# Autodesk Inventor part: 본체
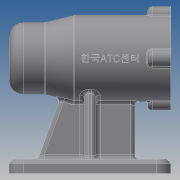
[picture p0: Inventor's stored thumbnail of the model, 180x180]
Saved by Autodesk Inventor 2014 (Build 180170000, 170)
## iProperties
Created: 2019-07
Part Number: 본체
Material: Generic
Document SubType Name: Modeling
Designer: kb541-07
Density: 1 g/cm^3
Appearance: Default
Author: kb541-07
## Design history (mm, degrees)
sketch "스케치1"
  geometry: L1 (-56, 0)-(56, 0); L2 (-56, 0)-(-56, 25); L3 (-56, 25)-(-31, 25); L4 (-31, 25)-(-11, 30); L5 (-11, 30)-(56, 30); L6 (56, 30)-(56, 0); 2 further points
  constraints: 12 end point, 2 perpendicular, 1 coincident, 1 horizontal, 1 midpoint, 1 parallel, 1 vertical
  dimensions: "d0" = 112 distance of L1.start L1.end; "d1" = 50 diameter of L3 L1; "d2" = 60 diameter of L5 L1; "d3" = 25 distance of L2.end L3.end; "d4" = 45 horizontal distance of L2.end L4.end
revolve "회전1" sketch "스케치1" stored, may be unused: angle "d5" = 90 deg
sketch "스케치2"
  geometry: C1 r 6 at (0, 30); C2 r 6 at (-30, 0); C3 r 6 at (0, -30); C4 r 6 at (30, 0); A1 r 30 centre (0, 0) between (0, 30) and (-30, 0) reference
  constraints: 4 centre point, 4 point on circle, 3 equal radius, 2 horizontal alignment, 2 vertical alignment
  dimensions: "d6" = 12 diameter of C1
extrude "돌출1" join sketch "스케치2" distance "d7" = 16; taper "d8" = 0 deg
sketch "스케치3"
  geometry: L1 (-56, -25)-(-56, 25) reference; L2 (-56, 25)-(-31, 25) reference; L3 (-31, 25)-(-11, 30) reference; L4 (-11, 30)-(40, 30) reference; L5 (40, 30)-(40, 36) reference; L6 (40, 36)-(56, 36) reference; L7 (56, 36)-(56, -36) reference; L8 (56, -36)-(40, -36) reference; L9 (40, -36)-(40, -30) reference; L10 (40, -30)-(-11, -30) reference; L11 (-11, -30)-(-31, -25) reference; L12 (-31, -25)-(-56, -25) reference; L13 (-56, 0)-(56, 0); L14 (-50, 0)-(-50, 10.5); L15 (-50, 10.5)-(-47, 10.5); L16 (-47, 10.5)-(-47, 16); L17 (-47, 16)-(-43, 16); L18 (-43, 16)-(-43, 17.5); L19 (-43, 17.5)-(-25, 17.5); L20 (-25, 17.5)-(-25, 21); L21 (-25, 21)-(-13, 21); L22 (-13, 21)-(-13, 24); L23 (-13, 24)-(41, 24); L24 (41, 24)-(41, 21); L25 (41, 21)-(56, 21); L26 (56, 21)-(56, 0); L27 (56, 5.97)-(56, 29.4) reference; 1 further point
  constraints: 28 end point, 7 perpendicular, 5 parallel, 2 midpoint, 2 point on line, 1 collinear
  dimensions: "d9" = 15 distance of L24.end L25.end; "d10" = 48 diameter of L23 L13; "d11" = 42 diameter of L25 L13; "d12" = 42 diameter of L21 L13; "d13" = 21 diameter of L15 L13; "d14" = 32 diameter of L17 L13; "d15" = 35 diameter of L19 L13; "d16" = 3 distance of L14.end L15.end; "d17" = 4 distance of L16.end L17.end; "d18" = 18 distance of L18.end L19.end; "d19" = 12 distance of L20.end L21.end; "d21" = 54 distance of L22.end L23.end
revolve "회전2" sketch "스케치3" stored, may be unused: angle "d22" = 90 deg
sketch "스케치5"
  geometry: L1 (-56, -70)-(56, -70); L2 (56, -70)-(56, -80); L3 (56, -80)-(-56, -80); L4 (-56, -80)-(-56, -70); L5 (-56, -25)-(-56, 25) reference; L6 (-56, 25)-(-31, 25) reference; L7 (-31, 25)-(-11, 30) reference; L8 (-11, 30)-(40, 30) reference; L9 (40, 30)-(40, 36) reference; L10 (40, 36)-(56, 36) reference; L11 (56, 36)-(56, 21) reference; L12 (56, 21)-(41, 21) reference; L13 (41, 21)-(41, 24) reference; L14 (41, 24)-(-13, 24) reference; L15 (-13, 24)-(-13, 21) reference; L16 (-13, 21)-(-25, 21) reference; L17 (-25, 21)-(-25, 17.5) reference; L18 (-25, 17.5)-(-43, 17.5) reference; L19 (-43, 17.5)-(-43, 16) reference; L20 (-43, 16)-(-47, 16) reference; L21 (-47, 16)-(-47, 10.5) reference; L22 (-47, 10.5)-(-50, 10.5) reference; L23 (-50, 10.5)-(-50, -10.5) reference; L24 (-50, -10.5)-(-47, -10.5) reference; L25 (-47, -10.5)-(-47, -16) reference; L26 (-47, -16)-(-43, -16) reference; L27 (-43, -16)-(-43, -17.5) reference; L28 (-43, -17.5)-(-25, -17.5) reference; L29 (-25, -17.5)-(-25, -21) reference; L30 (-25, -21)-(-13, -21) reference; L31 (-13, -21)-(-13, -24) reference; L32 (-13, -24)-(41, -24) reference; L33 (41, -24)-(41, -21) reference; L34 (41, -21)-(56, -21) reference; L35 (56, -21)-(56, -36) reference; L36 (56, -36)-(40, -36) reference; L37 (40, -36)-(40, -30) reference; L38 (40, -30)-(-11, -30) reference; L39 (-11, -30)-(-31, -25) reference; L40 (-31, -25)-(-56, -25) reference; L41 (56, 21)-(56, -21) reference; L42 (-56, -25)-(-56, 25) reference; L43 (-56, 0)-(56, 0); 1 further point
  constraints: 10 end point, 2 midpoint, 2 parallel, 1 collinear, 1 horizontal, 1 perpendicular
  dimensions: "d24" = 10 distance of L1.end L2.end; "d25" = 112 distance of L2.end L3.end; "d26" = 80 distance between parallel lines of L3 L43
extrude "돌출2" join sketch "스케치5" stored distance "d27" = 70; taper "d28" = 0 deg
node "작업 평면2"
sketch "스케치6"
  geometry: L1 (65, -70)-(-5, -70) reference; L2 (30, 0)-(30, -70); L3 (2, -70)-(10.346, -22.666); L4 (58, -70)-(49.654, -22.666); L5 (2, -70)-(58, -70); A1 r 30 centre (30, 0) between (10.346, -22.666) and (49.654, -22.666); 1 further point
  constraints: 8 end point, 2 point on circle, 2 symmetric about line, 1 centre point, 1 collinear, 1 midpoint, 1 point on line, 3 other
  dimensions: "d30" = 7 distance of L1.end L3.start; "d31" = 100 deg angle of L3 L1
extrude "돌출3" join sketch "스케치6" stored distance "d32" = 8; taper "d33" = 0 deg
sketch "스케치7"
  geometry: L1 (-56, -25)-(-56, 25) reference; L2 (-56, 25)-(-31, 25) reference; L3 (-31, 25)-(-11, 30) reference; L4 (-11, 30)-(40, 30) reference; L5 (40, 30)-(40, 36) reference; L6 (40, 36)-(56, 36) reference; L7 (56, 36)-(56, 21) reference; L8 (56, 21)-(41, 21) reference; L9 (41, 21)-(41, 24) reference; L10 (41, 24)-(-13, 24) reference; L11 (-13, 24)-(-13, 21) reference; L12 (-13, 21)-(-25, 21) reference; L13 (-25, 21)-(-25, 17.5) reference; L14 (-25, 17.5)-(-43, 17.5) reference; L15 (-43, 17.5)-(-43, 16) reference; L16 (-43, 16)-(-47, 16) reference; L17 (-47, 16)-(-47, 10.5) reference; L18 (-47, 10.5)-(-50, 10.5) reference; L19 (-50, 10.5)-(-50, -10.5) reference; L20 (-50, -10.5)-(-47, -10.5) reference; L21 (-47, -10.5)-(-47, -16) reference; L22 (-47, -16)-(-43, -16) reference; L23 (-43, -16)-(-43, -17.5) reference; L24 (-43, -17.5)-(-25, -17.5) reference; L25 (-25, -17.5)-(-25, -21) reference; L26 (-25, -21)-(-13, -21) reference; L27 (-13, -21)-(-13, -24) reference; L28 (-13, -24)-(41, -24) reference; L29 (41, -24)-(41, -21) reference; L30 (41, -21)-(56, -21) reference; L31 (56, -21)-(56, -36) reference; L32 (56, -36)-(40, -36) reference; L33 (40, -36)-(40, -30) reference; L34 (40, -30)-(4, -30) reference; L35 (4, -30)-(4, -70) reference; L36 (4, -70)-(56, -70) reference; L37 (56, -70)-(56, -80) reference; L38 (56, -80)-(-56, -80) reference; L39 (-56, -80)-(-56, -70) reference; L40 (-56, -70)-(-4, -70) reference; L41 (-4, -70)-(-4, -30) reference; L42 (-4, -30)-(-11, -30) reference; L43 (-11, -30)-(-31, -25) reference; L44 (-31, -25)-(-56, -25) reference; L45 (-36, -70)-(-20.57, -27.607); 1 further point
  constraints: 2 end point, 2 point on line
  dimensions: "d34" = 20 distance of L39.end L45.start; "d35" = 110 deg angle of L45 L40
feature "리브1" sketch "스케치7" dims "d36" = 1, "d37" = 8, "d38" = 0, "d39" = 0, "d40" = 1, "d41" = 1
sketch "스케치8"
  geometry: L1 (-56, -25)-(-56, 25) reference; L2 (-56, 25)-(-31, 25) reference; L3 (-31, 25)-(-11, 30) reference; L4 (-11, 30)-(40, 30) reference; L5 (40, 30)-(40, 36) reference; L6 (40, 36)-(56, 36) reference; L7 (56, 36)-(56, 21) reference; L8 (56, 21)-(41, 21) reference; L9 (41, 21)-(41, 24) reference; L10 (41, 24)-(-13, 24) reference; L11 (-13, 24)-(-13, 21) reference; L12 (-13, 21)-(-25, 21) reference; L13 (-25, 21)-(-25, 17.5) reference; L14 (-25, 17.5)-(-43, 17.5) reference; L15 (-43, 17.5)-(-43, 16) reference; L16 (-43, 16)-(-47, 16) reference; L17 (-47, 16)-(-47, 10.5) reference; L18 (-47, 10.5)-(-50, 10.5) reference; L19 (-50, 10.5)-(-50, -10.5) reference; L20 (-50, -10.5)-(-47, -10.5) reference; L21 (-47, -10.5)-(-47, -16) reference; L22 (-47, -16)-(-43, -16) reference; L23 (-43, -16)-(-43, -17.5) reference; L24 (-43, -17.5)-(-25, -17.5) reference; L25 (-25, -17.5)-(-25, -21) reference; L26 (-25, -21)-(-13, -21) reference; L27 (-13, -21)-(-13, -24) reference; L28 (-13, -24)-(41, -24) reference; L29 (41, -24)-(41, -21) reference; L30 (41, -21)-(56, -21) reference; L31 (56, -21)-(56, -36) reference; L32 (56, -36)-(40, -36) reference; L33 (40, -36)-(40, -30) reference; L34 (40, -30)-(4, -30) reference; L35 (4, -30)-(4, -70) reference; L36 (4, -70)-(56, -70) reference; L37 (56, -70)-(56, -80) reference; L38 (56, -80)-(-56, -80) reference; L39 (-56, -80)-(-56, -70) reference; L40 (-56, -70)-(-36, -70) reference; L41 (-36, -70)-(-20.57, -27.607) reference; L42 (-20.57, -27.607)-(-31, -25) reference; L43 (-31, -25)-(-56, -25) reference; L44 (4, -30)-(40, -30) reference; L45 (31, -30)-(31, -70); 1 further point
  constraints: 2 end point, 2 point on line, 1 perpendicular
  dimensions: "d42" = 25 distance between parallel lines of L37 L45
feature "리브2" sketch "스케치8" dims "d43" = 1, "d44" = 8, "d45" = 0, "d46" = 0, "d47" = 1, "d48" = 1
fillet "모깎기1" dims "d51" = 10
sketch "스케치10"
  geometry: C1 r 3 at (0, 60); C2 r 3 at (92, 60); C3 r 3 at (0, 10); C4 r 3 at (92, 10); A1 r 10 centre (0, 60) between (0, 70) and (-10, 60) reference; A2 r 10 centre (0, 10) between (-10, 10) and (0, 0) reference; A3 r 10 centre (92, 10) between (92, 0) and (102, 10) reference; A4 r 10 centre (92, 60) between (102, 60) and (92, 70) reference; 1 further point
  constraints: 4 centre point, 4 coincident, 3 equal radius
  dimensions: "d52" = 6 diameter of C1
extrude "돌출4" cut sketch "스케치10" stored distance "d53" = 8; taper "d54" = 0 deg
fillet "모깎기2" dims "d55" = 3
fillet "모깎기3" dims "d56" = 0.3
fillet "모깎기4" dims "d57" = 3
fillet "모깎기5" dims "d58" = 1
fillet "모깎기6" dims "d59" = 3
sketch "스케치11"
  geometry: C1 r 21 at (30, 0) reference; A1 r 30 centre (30, 0) between (23.229, 29.226) and (0.774, 6.771) reference; A2 r 30 centre (30, 0) between (59.226, 6.771) and (36.771, 29.226) reference; 2 further points
  constraints: 2 vertical alignment, 1 coincident, 3 other
hole "구멍1" sketch "스케치11" at (30, 30) diameter "d60" = 3.242; stored, may be unused: countersink angle "d64" = 90 deg, drill point angle "d66" = 118 deg; dims "d61" = 8, "d62" = 4, "d63" = 2, "d65" = 11
chamfer "모따기1" distance "d70" = 1; stored, may be unused: second distance "d71" = 2, angle "d72" = 45 deg
node "작업 평면3"
sketch "스케치12"
  geometry: L1 (56, 6.771)-(56, 29.226) reference; L2 (56, -29.226)-(56, -6.771) reference; L3 (56, 5.998)-(56, -5.998) reference; L4 (-56, -15)-(-56, 15) reference; L5 (-56, 0)-(56, 0); 2 further points
  constraints: 2 end point, 2 midpoint, 1 point on line, 1 other
  dimensions: "d74" = 42 distance from line of L1 point (14, 0)
feature "엠보싱1" sketch "스케치12" dims "d0" = 112, "d1" = 50, "d2" = 60, "d3" = 25, "d4" = 45, "d75" = 0.5, "d76" = 0
fillet "모깎기7" dims "d77" = 3
chamfer "모따기2" distance "d78" = 3; stored, may be unused: second distance "d79" = 2, angle "d80" = 45 deg
node "솔리드1"
pattern_circular "원형 패턴1" dims angle "d68" = 360 deg
node "절단 모서리 투영1"
node "절단 모서리 투영2"
node "절단 모서리 투영3"
node "절단 모서리 투영4"
other parameters: "d29" = -56, "d73" = 116.5
